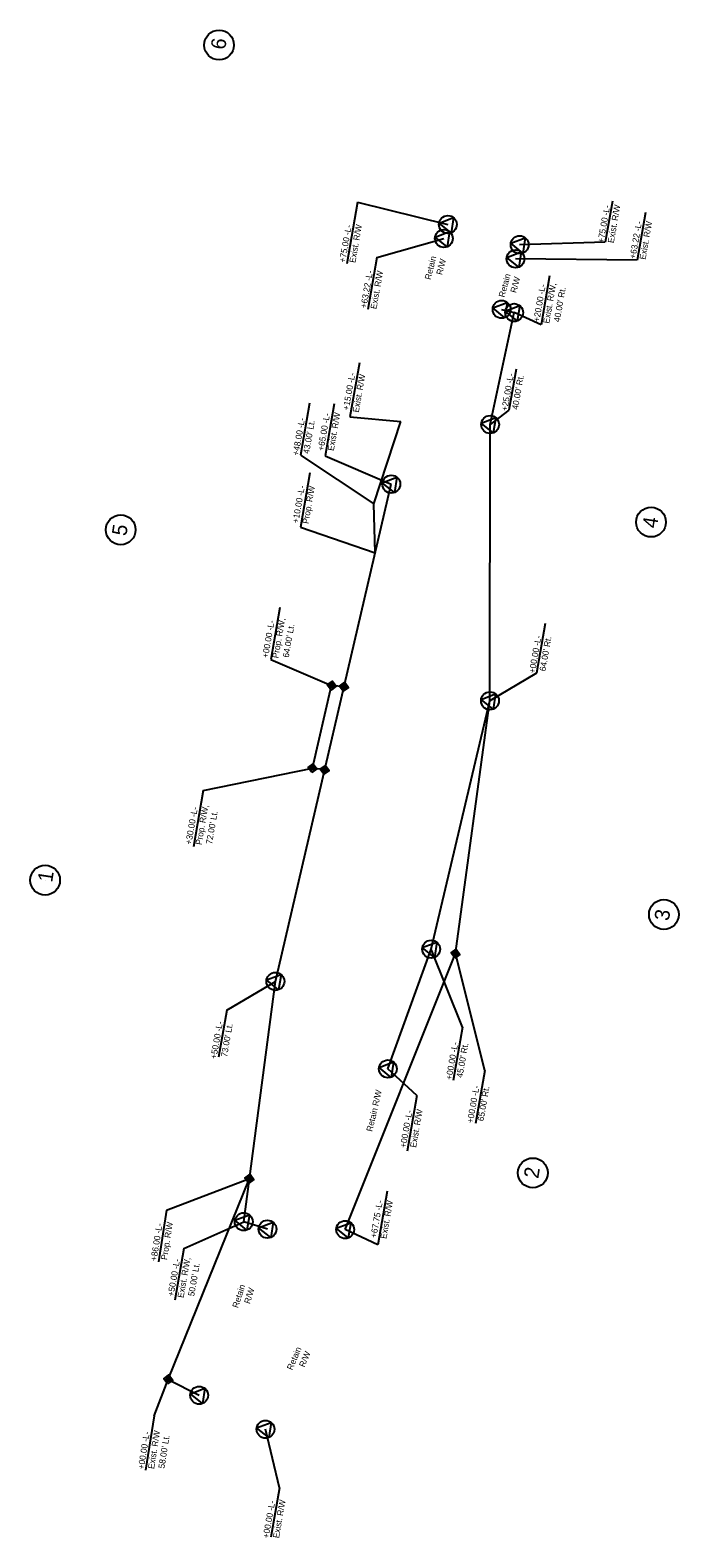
# Model space of a CAD drawing. Extents: x 1699108 to 1699630, y 708161 to 709375.
import ezdxf

# ---------------------------------------------------------------- set-up
doc = ezdxf.new("R2010")
doc.units = 0
for name, color, linetype in [('Analysis', 7, 'Continuous'), ('Exist Right of Way Line', 7, 'Continuous'), ('J Pole Pow Tel CELL', 7, 'Continuous'), ('Power Line UBO Text', 7, 'Continuous'), ('Prop Approach Slab', 7, 'Continuous'), ('Prop OH Pow Lines', 7, 'Continuous'), ('Prop OH Pow Tel Lines', 7, 'Continuous'), ('Prop Roadway Bridge', 7, 'Continuous'), ('Prop UG Tel Cables', 7, 'Continuous'), ('Pue Linestyle', 7, 'Continuous'), ('Telephone Line UBO Text', 7, 'Continuous'), ('UBO Telephone Arrow CELL', 7, 'Continuous')]:
    doc.layers.add(name, color=color, linetype=linetype)

msp = doc.modelspace()

# ---------------------------------------------------------------- linework, layer by layer
at = {"layer": 'Analysis'}
for p, q in [((1699478.1, 709057.7), (1699497.5, 709147.9)), ((1699487.4, 709150.5), (1699497.5, 709147.9)), ((1699478, 708835.1), (1699478.1, 709057.7)), ((1699305.2, 708609), (1699398.5, 709009.7)), ((1699430.6, 708635), (1699478, 708835.1)), ((1699395.8, 708538.5), (1699430.6, 708635)), ((1699279.7, 708415.4), (1699305.2, 708609)), ((1699298.8, 708409.4), (1699279.7, 708415.4))]:
    msp.add_line(p, q, dxfattribs=at)
at = {"layer": 'Exist Right of Way Line'}
for p, q in [((1699450.3, 708631.4), (1699478, 708835.1)), ((1699361.4, 708409), (1699450.3, 708631.4)), ((1699218.9, 708288.3), (1699284.3, 708450.1)), ((1699218.9, 708288.3), (1699243.8, 708275.5))]:
    msp.add_line(p, q, dxfattribs=at)
at = {"layer": 'J Pole Pow Tel CELL'}
for p, q in [((1699384.6, 708993.9), (1699406.3, 709060.2)), ((1699385.6, 708954.4), (1699384.6, 708993.9))]:
    msp.add_line(p, q, dxfattribs=at)
at = {"layer": 'Power Line UBO Text'}
for p, q in [((1699259.8, 709363.5), (1699259.8, 709363.5)), ((1699180.6, 708972.9), (1699180.6, 708972.9)), ((1699607.7, 708979.1), (1699607.7, 708979.1)), ((1699119.7, 708690.6), (1699119.7, 708690.6)), ((1699618.1, 708662.9), (1699618.1, 708662.9)), ((1699512.5, 708454.7), (1699512.5, 708454.7))]:
    msp.add_line(p, q, dxfattribs=at)
for centre in [(1699259.8, 709363.5), (1699180.6, 708972.9), (1699607.7, 708979.1), (1699119.7, 708690.6), (1699618.1, 708662.9), (1699512.5, 708454.7)]:
    msp.add_circle(centre, 12, dxfattribs=at)
at = {"layer": 'Prop Approach Slab'}
for points in [[(1699350, 708843.8), (1699347, 708847.9), (1699351.1, 708850.9), (1699354.1, 708846.8)], [(1699350.3, 708845.6), (1699348.8, 708847.7), (1699350.8, 708849.2), (1699352.3, 708847.1)], [(1699359.9, 708842.9), (1699356.9, 708847), (1699361, 708850), (1699364, 708845.9)], [(1699360.2, 708844.6), (1699358.7, 708846.7), (1699360.8, 708848.2), (1699362.3, 708846.1)], [(1699334.5, 708777.2), (1699331.5, 708781.3), (1699335.6, 708784.3), (1699338.6, 708780.2)], [(1699334.7, 708779), (1699333.2, 708781), (1699335.3, 708782.5), (1699336.8, 708780.5)], [(1699344.3, 708776), (1699341.3, 708780.1), (1699345.5, 708783.1), (1699348.5, 708779)], [(1699344.6, 708777.7), (1699343.1, 708779.8), (1699345.2, 708781.3), (1699346.7, 708779.2)], [(1699449.7, 708627.8), (1699446.7, 708631.9), (1699450.8, 708634.9), (1699453.8, 708630.8)], [(1699450, 708629.6), (1699448.5, 708631.7), (1699450.6, 708633.2), (1699452.1, 708631.1)], [(1699283.7, 708446.5), (1699280.7, 708450.6), (1699284.8, 708453.6), (1699287.8, 708449.5)], [(1699284, 708448.3), (1699282.5, 708450.4), (1699284.6, 708451.9), (1699286.1, 708449.8)], [(1699218.4, 708284.8), (1699215.4, 708288.9), (1699219.5, 708291.9), (1699222.5, 708287.8)], [(1699218.6, 708286.6), (1699217.1, 708288.6), (1699219.2, 708290.1), (1699220.7, 708288.1)]]:
    msp.add_lwpolyline(points, close=True, dxfattribs=at)
at = {"layer": 'Prop OH Pow Lines'}
for p, q in [((1699371.3, 709237), (1699362.6, 709187.2)), ((1699576.7, 709237.7), (1699570.9, 709204.6)), ((1699603.2, 709228.6), (1699596.5, 709190.1)), ((1699386.8, 709192.4), (1699379.5, 709150.3)), ((1699526, 709177.5), (1699519.1, 709138)), ((1699499, 709102.3), (1699493.3, 709069.2)), ((1699352.5, 709074.4), (1699345.2, 709032.6)), ((1699522.5, 708897.5), (1699515.5, 708857.4)), ((1699266.1, 708585.9), (1699259.5, 708547.9)), ((1699455.9, 708572), (1699448.4, 708529.2)), ((1699419.1, 708517), (1699411.2, 708472.3)), ((1699395.1, 708440.1), (1699387.6, 708396.8)), ((1699231.5, 708393.8), (1699224.2, 708352.3)), ((1699308.4, 708201), (1699301.4, 708161.2))]:
    msp.add_line(p, q, dxfattribs=at)
for points in [[(1699371.3, 709237), (1699444.1, 709218.9)], [(1699386.8, 709192.4), (1699440.9, 709207.6)], [(1699570.9, 709204.6), (1699501.9, 709202.6)], [(1699596.5, 709190.1), (1699498.6, 709191.2)], [(1699519.1, 709138), (1699497.5, 709147.9)], [(1699493.3, 709069.2), (1699478.1, 709057.7)], [(1699345.2, 709032.6), (1699398.5, 709009.7)], [(1699515.5, 708857.4), (1699478, 708835.1)], [(1699455.9, 708572), (1699430.6, 708635)], [(1699266.1, 708585.9), (1699305.2, 708609)], [(1699419.1, 708517), (1699395.8, 708538.5)], [(1699231.5, 708393.8), (1699279.7, 708415.4)], [(1699387.6, 708396.8), (1699361.4, 708409)], [(1699308.4, 708201), (1699297.2, 708248.1)]]:
    msp.add_lwpolyline(points, dxfattribs=at)
at = {"layer": 'Prop OH Pow Tel Lines'}
for p, q in [((1699473.8, 708537.2), (1699466.3, 708494.4)), ((1699217.6, 708424.8), (1699211, 708383.1)), ((1699207.6, 708259), (1699200.7, 708215.2))]:
    msp.add_line(p, q, dxfattribs=at)
for points in [[(1699473.8, 708537.2), (1699450.3, 708631.4)], [(1699217.6, 708424.8), (1699284.3, 708450.1)], [(1699207.6, 708259), (1699218.9, 708288.3)]]:
    msp.add_lwpolyline(points, dxfattribs=at)
at = {"layer": 'Prop Roadway Bridge'}
for p, q in [((1699308.8, 708910.4), (1699301.4, 708868.5)), ((1699247.1, 708762.8), (1699239.2, 708717.5))]:
    msp.add_line(p, q, dxfattribs=at)
for points in [[(1699301.4, 708868.5), (1699350.5, 708847.4)], [(1699247.1, 708762.8), (1699335, 708780.8)]]:
    msp.add_lwpolyline(points, dxfattribs=at)
at = {"layer": 'Prop UG Tel Cables'}
for p, q in [((1699372.8, 709107.3), (1699365.2, 709063.9)), ((1699332.7, 709074.8), (1699325.4, 709033)), ((1699333, 709018.8), (1699325.3, 708974.9))]:
    msp.add_line(p, q, dxfattribs=at)
for points in [[(1699365.2, 709063.9), (1699406.3, 709060.2)], [(1699325.4, 709033), (1699384.6, 708993.9)], [(1699325.3, 708974.9), (1699385.6, 708954.4)]]:
    msp.add_lwpolyline(points, dxfattribs=at)
at = {"layer": 'Pue Linestyle'}
for p, q in [((1699444.1, 709218.9), (1699444.1, 709218.9)), ((1699440.9, 709207.6), (1699440.9, 709207.6)), ((1699498.6, 709191.2), (1699498.6, 709191.2)), ((1699501.9, 709202.6), (1699501.9, 709202.6)), ((1699487.4, 709150.5), (1699487.4, 709150.5)), ((1699497.5, 709147.9), (1699497.5, 709147.9)), ((1699478.1, 709057.7), (1699478.1, 709057.7)), ((1699398.5, 709009.7), (1699398.5, 709009.7)), ((1699350.5, 708847.4), (1699350.5, 708847.4)), ((1699360.5, 708846.4), (1699360.5, 708846.4)), ((1699478, 708835.1), (1699478, 708835.1)), ((1699335, 708780.8), (1699335, 708780.8)), ((1699344.9, 708779.5), (1699344.9, 708779.5)), ((1699430.6, 708635), (1699430.6, 708635)), ((1699450.3, 708631.4), (1699450.3, 708631.4)), ((1699305.2, 708609), (1699305.2, 708609)), ((1699395.8, 708538.5), (1699395.8, 708538.5)), ((1699284.3, 708450.1), (1699284.3, 708450.1)), ((1699279.7, 708415.4), (1699279.7, 708415.4)), ((1699298.8, 708409.4), (1699298.8, 708409.4)), ((1699361.4, 708409), (1699361.4, 708409)), ((1699218.9, 708288.3), (1699218.9, 708288.3)), ((1699243.8, 708275.5), (1699243.8, 708275.5)), ((1699297.2, 708248.1), (1699297.2, 708248.1))]:
    msp.add_line(p, q, dxfattribs=at)
for points in [[(1699446.7, 709212.2), (1699437, 709220), (1699448.7, 709224.5)], [(1699443.5, 709200.8), (1699433.8, 709208.7), (1699445.4, 709213.2)], [(1699504.4, 709195.8), (1699494.7, 709203.7), (1699506.4, 709208.2)], [(1699501.2, 709184.5), (1699491.5, 709192.3), (1699503.2, 709196.8)], [(1699489.9, 709143.7), (1699480.2, 709151.6), (1699491.9, 709156.1)], [(1699500, 709141.2), (1699490.3, 709149), (1699502, 709153.5)], [(1699480.7, 709051), (1699471, 709058.8), (1699482.7, 709063.3)], [(1699401, 709002.9), (1699391.3, 709010.8), (1699403, 709015.3)], [(1699480.5, 708828.3), (1699470.8, 708836.2), (1699482.5, 708840.7)], [(1699433.2, 708628.3), (1699423.5, 708636.2), (1699435.1, 708640.6)], [(1699307.8, 708602.3), (1699298.1, 708610.2), (1699309.8, 708614.7)], [(1699398.4, 708531.7), (1699388.7, 708539.6), (1699400.3, 708544.1)], [(1699282.3, 708408.7), (1699272.6, 708416.5), (1699284.2, 708421)], [(1699301.4, 708402.7), (1699291.7, 708410.5), (1699303.3, 708415)], [(1699363.9, 708402.3), (1699354.2, 708410.1), (1699365.9, 708414.6)], [(1699246.4, 708268.8), (1699236.7, 708276.7), (1699248.4, 708281.2)], [(1699299.8, 708241.4), (1699290.1, 708249.2), (1699301.7, 708253.7)]]:
    msp.add_lwpolyline(points, close=True, dxfattribs=at)
for centre in [(1699440.9, 709207.6), (1699444.1, 709218.9), (1699501.9, 709202.6), (1699498.6, 709191.2), (1699487.4, 709150.5), (1699497.5, 709147.9), (1699478.1, 709057.7), (1699398.5, 709009.7), (1699478, 708835.1), (1699430.6, 708635), (1699305.2, 708609), (1699395.8, 708538.5), (1699279.7, 708415.4), (1699298.8, 708409.4), (1699361.4, 708409), (1699243.8, 708275.5), (1699297.2, 708248.1)]:
    msp.add_circle(centre, 7.2, dxfattribs=at)
at = {"layer": 'UBO Telephone Arrow CELL'}
for p, q in [((1699335, 708780.8), (1699350.5, 708847.4)), ((1699360.5, 708846.4), (1699350.5, 708847.4)), ((1699344.9, 708779.5), (1699335, 708780.8))]:
    msp.add_line(p, q, dxfattribs=at)

# ---------------------------------------------------------------- texts
at = {"layer": 'Prop OH Pow Lines'}
for s, rotation, p in [('+75.00 -L-', 80.0835, (1699569.5, 709203.8)), ('Exist. R/W', 80.0835, (1699577.7, 709203.6)), ('+75.00 -L-', 80.0835, (1699361.4, 709187.9)), ('Exist. R/W', 80.0835, (1699369.6, 709187.7)), ('+63.22 -L-', 80.0835, (1699595.2, 709191)), ('Exist. R/W', 80.0835, (1699603.3, 709190.3)), ('Retain', 76.0752, (1699430.2, 709174)), ('R/W', 76.0752, (1699439.5, 709177.9)), ('+63.22 -L-', 80.0835, (1699378.5, 709151.1)), ('Exist. R/W', 80.0835, (1699386.6, 709150.4)), ('Retain', 75.0331, (1699489.7, 709159.8)), ('R/W', 75.0331, (1699499.1, 709163.4)), ('+20.00 -L-', 80.0835, (1699517.7, 709140.1)), ('Exist. R/W, ', 80.0835, (1699525.7, 709138.8)), ("40.00' Rt.", 80.0835, (1699534.2, 709140)), ('+25.00 -L-', 80.0835, (1699492, 709068.3)), ("40.00' Rt.", 80.0835, (1699500.5, 709069.4)), ('+65.00 -L-', 80.0835, (1699344, 709036.3)), ('Exist. R/W', 80.0835, (1699352.2, 709036.2)), ('+00.00 -L-', 80.0835, (1699514.2, 708857)), ("64.00' Rt.", 80.0835, (1699522.7, 708858.6)), ('+50.00 -L-', 80.0835, (1699257.7, 708546.2)), ("73.00' Lt.", 80.0835, (1699266.2, 708547.8)), ('+00.00 -L-', 80.0835, (1699447.2, 708529.4)), ("45.00' Rt.", 80.0835, (1699455.8, 708531.1)), ('Retain R/W', 76.8797, (1699383.2, 708487.6)), ('+00.00 -L-', 80.0835, (1699410.3, 708474.6)), ('Exist. R/W', 80.0835, (1699418.5, 708474.8)), ('+67.75 -L-', 80.0835, (1699386.5, 708402)), ('Exist. R/W', 80.0835, (1699394.6, 708401.3)), ('+50.00 -L-', 80.0835, (1699223.2, 708354.9)), ('Exist. R/W,', 80.0835, (1699231.2, 708353.7)), ("50.00' Lt.", 80.0835, (1699239.7, 708355)), ('Retain', 72.3218, (1699275.1, 708345.5)), ('R/W', 72.3218, (1699284.6, 708348.8)), ('Retain', 67.0447, (1699318.8, 708295.4)), ('R/W', 67.0447, (1699328.6, 708297.7)), ('+00.00 -L-', 80.0835, (1699299.8, 708160)), ('Exist. R/W', 80.0835, (1699308.1, 708160.1))]:
    msp.add_text(s, height=5, rotation=rotation, dxfattribs=at).set_placement(p)
at = {"layer": 'Prop OH Pow Tel Lines'}
for s, rotation, p in [('+00.00 -L-', 80.0835, (1699464.3, 708494.5)), ("65.00' Rt.", 80.0835, (1699472.8, 708496.1)), ('+86.00 -L-', 81.0546, (1699209.5, 708383.4)), ('Prop. R/W', 81.0546, (1699217.9, 708384.3)), ('+00.00 -L-', 81.0546, (1699199.3, 708215.6)), ('Exist. R/W', 81.0546, (1699207.5, 708215.9)), ("58.00' Lt.", 81.0546, (1699215.8, 708216.3))]:
    msp.add_text(s, height=5, rotation=rotation, dxfattribs=at).set_placement(p)
at = {"layer": 'Prop Roadway Bridge'}
for s, p in [('+00.00 -L-', (1699299.3, 708869.3)), ('Prop. R/W,', (1699307.5, 708869.1)), ("64.00' Lt.", (1699315.9, 708869.6)), ('+30.00 -L-', (1699237.5, 708719)), ('Prop. R/W, ', (1699245.7, 708718.7)), ("72.00' Lt.", (1699254.1, 708719.2))]:
    msp.add_text(s, height=5, rotation=80.0835, dxfattribs=at).set_placement(p)
at = {"layer": 'Prop UG Tel Cables'}
for s, p in [('+15.00 -L-', (1699364.3, 709068.8)), ('Exist. R/W', (1699372.3, 709067.1)), ('+48.00 -L-', (1699323.8, 709032.4)), ("43.00' Lt.", (1699332.3, 709033.8)), ('Prop. R/W', (1699331.8, 708977.4)), ('+10.00 -L-', (1699323.7, 708977.9))]:
    msp.add_text(s, height=5, rotation=80.0835, dxfattribs=at).set_placement(p)
at = {"layer": 'Telephone Line UBO Text'}
for s, p in [('6', (1699264.7, 709359.3)), ('5', (1699185.1, 708967.5)), ('4', (1699612.4, 708973.6)), ('1', (1699125.4, 708688.4)), ('3', (1699622, 708657.3)), ('2', (1699516.9, 708449.7))]:
    msp.add_text(s, height=11.9, rotation=81.2267, dxfattribs=at).set_placement(p)

doc.saveas('drawing.dxf')
